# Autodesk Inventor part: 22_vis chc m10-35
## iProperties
Shininess: 20.0
Length Units: 11270
Angle Units: 11279
Time Units: 11290
Mass Units: 11283
Length Display Precision: 3
Angle Display Precision: 2
Created: 2000-10
Part Number: 22_vis chc m10-35
Material: Par défaut
Document SubType Name: Modélisation
Density: 0.0
Volumn: 0.0
Area: 0.0
PropertySet Name: Model Information
Control State: 0
Master: False
Checked Out: False
Author: Laurent GAUTHERON
